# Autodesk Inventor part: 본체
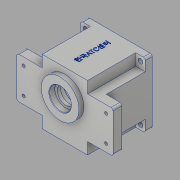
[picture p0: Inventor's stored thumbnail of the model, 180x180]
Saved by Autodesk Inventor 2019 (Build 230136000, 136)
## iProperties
Created: 2020-01
Part Number: 본체
Material: 알루미늄 6061
Document SubType Name: Modeling
Designer: 323-19
Density: 2.7 g/cm^3
Appearance: 알루미늄 - 평지
Mass: 876.381 g
Surface Area: 793.348 cm^2
Volume: 324.585 cm^3
Author: 323-19
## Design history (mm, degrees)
sketch "스케치1"
  geometry: L1 (-47, -47)-(47, -47); L2 (47, -47)-(47, 47); L3 (47, 47)-(-47, 47); L4 (-47, 47)-(-47, -47); L5 (-47, -47)-(47, 47); L6 (47, -47)-(-47, 47); 1 further point
  constraints: 12 end point, 2 midpoint, 2 parallel, 1 horizontal, 1 perpendicular
  dimensions: "d0" = 94 distance of L3.end L2.end; "d1" = 94 distance of L2.end L1.end
extrude "돌출1" new body sketch "스케치1" distance "d2" = 80; taper "d3" = 0 deg
sketch "스케치2"
  geometry: L1 (-70, 30)-(70, 30); L2 (70, 30)-(70, -30); L3 (70, -30)-(-70, -30); L4 (-70, -30)-(-70, 30); L5 (-70, 30)-(70, -30); L6 (70, 30)-(-70, -30); 1 further point
  constraints: 12 end point, 2 midpoint, 2 parallel, 1 horizontal, 1 perpendicular
  dimensions: "d4" = 140 distance of L2.end L3.end; "d5" = 60 distance of L1.end L2.end
extrude "돌출2" join sketch "스케치2" distance "d6" = 13; taper "d7" = 0 deg
sketch "스케치3"
  geometry: C1 r 27.5 at (0, 11); 1 further point
  constraints: 1 centre point, 1 vertical alignment
  dimensions: "d8" = 55 diameter of C1; "d9" = 11 distance of point (0, 0) C1.centre
extrude "돌출3" join sketch "스케치3" distance "d10" = 7; taper "d11" = 0 deg
sketch "스케치4"
  geometry: L1 (70, -30)-(47, -30) reference; L2 (47, -30)-(47, -47) reference; L3 (47, -47)-(-47, -47) reference; L4 (-47, -47)-(-47, -30) reference; L5 (-47, -30)-(-70, -30) reference; L6 (-70, -30)-(-70, 30) reference; L7 (-70, 30)-(-47, 30) reference; L8 (-47, 30)-(-47, 47) reference; L9 (-47, 47)-(47, 47) reference; L10 (47, 47)-(47, 30) reference; L11 (47, 30)-(70, 30) reference; L12 (70, 30)-(70, -30) reference; L13 (47, 30)-(47, 47) reference; L14 (47, 47)-(33, 47); L15 (33, 47)-(33, 30); L16 (33, 30)-(47, 30); L17 (47, 30)-(47, 47); L18 (-47, -47)-(47, -47) reference; L19 (47, -47)-(33, -47); L20 (33, -47)-(33, -30); L21 (33, -30)-(47, -30); L22 (47, -30)-(47, -47); L23 (-47, -47)-(-33, -47); L24 (-33, -47)-(-33, -30); L25 (-33, -30)-(-47, -30); L26 (-47, -30)-(-47, -47); L27 (-47, 47)-(-33, 47); L28 (-33, 47)-(-33, 30); L29 (-33, 30)-(-47, 30); L30 (-47, 30)-(-47, 47); C1 r 27.5 at (0, 11) reference; 1 further point
  constraints: 32 end point, 8 parallel, 4 horizontal, 4 perpendicular
  dimensions: "d12" = 14 distance of L16.end L15.end; "d13" = 17 distance of L15.end L14.end; "d14" = 14 distance of L20.end L21.end; "d15" = 17 distance of L19.end L20.end; "d16" = 14 distance of L25.end L24.end; "d17" = 17 distance of L24.end L23.end; "d18" = 14 distance of L28.end L29.end; "d19" = 17 distance of L27.end L28.end
extrude "돌출4" cut sketch "스케치4" distance "d20" = 70; taper "d21" = 0 deg
sketch "스케치5"
  geometry: C1 r 40 at (0, 0); 1 further point
  constraints: 1 centre point, 1 coincident
  dimensions: "d22" = 80 diameter of C1
extrude "돌출5" cut sketch "스케치5" distance "d23" = 71; taper "d24" = 0 deg
sketch "스케치6"
  geometry: C1 r 43 at (0, 0); 1 further point
  constraints: 1 centre point, 1 coincident
  dimensions: "d25" = 86 diameter of C1
extrude "돌출6" cut sketch "스케치6" distance "d26" = 9; taper "d27" = 0 deg
sketch "스케치7"
  geometry: C1 r 21 at (0, 11); C2 r 15 at (0, -20); 1 further point
  constraints: 2 centre point, 2 vertical alignment
  dimensions: "d28" = 42 diameter of C1; "d29" = 30 diameter of C2; "d30" = 11 distance of point (0, 0) C1.centre; "d31" = 20 distance of point (0, 0) C2.centre
extrude "돌출7" join sketch "스케치7" distance "d32" = 7; taper "d33" = 0 deg
sketch "스케치8"
  geometry: L1 (-47, -30)-(-47, 30) reference; L2 (-47, 30)-(-33, 30) reference; L3 (-33, 30)-(-33, 47) reference; L4 (-33, 47)-(33, 47) reference; L5 (33, 47)-(33, 30) reference; L6 (33, 30)-(47, 30) reference; L7 (47, 30)-(47, -30) reference; L8 (47, -30)-(33, -30) reference; L9 (33, -30)-(33, -47) reference; L10 (33, -47)-(-33, -47) reference; L11 (-33, -47)-(-33, -30) reference; L12 (-33, -30)-(-47, -30) reference; C1 r 40 at (0, 0) reference; C2 r 17.5 at (0, 11); A1 r 21 centre (0, 11) between (8.978, -7.984) and (-8.978, -7.984) reference; A2 r 15 centre (0, -20) between (-8.978, -7.984) and (8.978, -7.984) reference; 1 further point
  constraints: 1 centre point, 1 coincident
  dimensions: "d34" = 35 diameter of C2
extrude "돌출8" cut sketch "스케치8" distance "d35" = 10; taper "d36" = 0 deg
sketch "스케치9"
  geometry: L1 (-47, -30)-(-47, 30) reference; L2 (-47, 30)-(-33, 30) reference; L3 (-33, 30)-(-33, 47) reference; L4 (-33, 47)-(33, 47) reference; L5 (33, 47)-(33, 30) reference; L6 (33, 30)-(47, 30) reference; L7 (47, 30)-(47, -30) reference; L8 (47, -30)-(33, -30) reference; L9 (33, -30)-(33, -47) reference; L10 (33, -47)-(-33, -47) reference; L11 (-33, -47)-(-33, -30) reference; L12 (-33, -30)-(-47, -30) reference; C1 r 17.5 at (0, 11) reference; C2 r 40 at (0, 0) reference; C3 r 11 at (0, -20); A1 r 21 centre (0, 11) between (8.978, -7.984) and (-8.978, -7.984) reference; A2 r 15 centre (0, -20) between (-8.978, -7.984) and (8.978, -7.984) reference; 1 further point
  constraints: 1 centre point, 1 coincident
  dimensions: "d37" = 22 diameter of C3
extrude "돌출9" cut sketch "스케치9" distance "d38" = 7; taper "d39" = 0 deg
sketch "스케치10"
  geometry: L1 (-33, -27)-(-33, -10) reference; L2 (-33, -10)-(-70, -10) reference; L3 (-70, -10)-(-70, 50) reference; L4 (-70, 50)-(-33, 50) reference; L5 (-33, 50)-(-33, 67) reference; L6 (-33, 67)-(33, 67) reference; L7 (33, 67)-(33, 50) reference; L8 (33, 50)-(70, 50) reference; L9 (70, 50)-(70, -10) reference; L10 (70, -10)-(33, -10) reference; L11 (33, -10)-(33, -27) reference; L12 (33, -27)-(-33, -27) reference; C1 r 11 at (0, 0) reference; C2 r 17.5 at (0, 31) reference; C3 r 40 at (0, 20) reference; C4 r 9.5 at (0, 0); A1 r 21 centre (0, 31) between (8.978, 12.016) and (-8.978, 12.016) reference; A2 r 15 centre (0, 0) between (-8.978, 12.016) and (8.978, 12.016) reference; 1 further point
  constraints: 1 centre point, 1 coincident
  dimensions: "d40" = 19 diameter of C4
extrude "돌출10" cut sketch "스케치10" distance "d41" = 3; taper "d42" = 0 deg
sketch "스케치11"
  geometry: C1 r 27.5 at (0, 0) reference; C2 r 16 at (0, 0); 1 further point
  constraints: 1 centre point, 1 coincident
  dimensions: "d43" = 32 diameter of C2
extrude "돌출11" cut sketch "스케치11" distance "d44" = 8.3; taper "d45" = 0 deg
sketch "스케치12"
  geometry: L1 (33, -41)-(33, -58) reference; L2 (33, -58)-(-33, -58) reference; L3 (-33, -58)-(-33, -41) reference; L4 (-33, -41)-(-70, -41) reference; L5 (-70, -41)-(-70, 19) reference; L6 (-70, 19)-(-33, 19) reference; L7 (-33, 19)-(-33, 36) reference; L8 (-33, 36)-(33, 36) reference; L9 (33, 36)-(33, 19) reference; L10 (33, 19)-(70, 19) reference; L11 (70, 19)-(70, -41) reference; L12 (70, -41)-(33, -41) reference; C1 r 16 at (0, 0) reference; C2 r 12.5 at (0, 0); 1 further point
  constraints: 1 centre point, 1 coincident
  dimensions: "d46" = 25 diameter of C2
extrude "돌출12" cut sketch "스케치12" distance "d47" = 4.7; taper "d48" = 0 deg
sketch "스케치13"
  geometry: L1 (47, 47)-(47, -47) reference; L2 (47, -47)-(-47, -47) reference; L3 (-47, -47)-(-47, 47) reference; L4 (-47, 47)-(47, 47) reference; L5 (35.778, 3.994)-(39.8, 3.994); L6 (35.778, -3.994)-(39.8, -3.994); C1 r 43 at (0, 0) reference; C2 r 40 at (0, 0) reference; A1 r 36 centre (0, 0) between (36, 0) and (35.778, 3.994); A2 r 4 centre (36, 0) between (35.778, 3.994) and (35.778, -3.994); A3 r 40 centre (0, 0) between (39.8, 3.994) and (39.8, -3.994) reference; A4 r 40 centre (0, 0) between (39.8, -3.994) and (39.8, 3.994); 1 further point
  constraints: 9 point on circle, 4 end point, 3 centre point, 2 coincident, 1 horizontal, 1 horizontal alignment, 1 parallel
  dimensions: "d49" = 72 diameter of A1; "d50" = 8 diameter of A2
extrude "돌출13" join sketch "스케치13" stored distance "d51" = 4.7; taper "d52" = 0 deg
sketch "스케치14"
  geometry: A1 r 4 centre (-36, 0) between (-35.778, -3.994) and (-35.778, 3.994) reference; A2 r 4 centre (36, 0) between (35.778, 3.994) and (35.778, -3.994) reference; 3 further points
  constraints: 2 coincident
hole "구멍1" sketch "스케치14" at (-36, 0), (36, 0) diameter "d53" = 3.242; stored, may be unused: countersink angle "d57" = 90 deg, drill point angle "d59" = 118 deg; dims "d54" = 7, "d55" = 4, "d56" = 2, "d58" = 9
sketch "스케치16"
  geometry: L1 (47, 47)-(47, -47) reference; L2 (47, -47)-(-47, -47) reference; L3 (-47, -47)-(-47, 47) reference; L4 (-47, 47)-(47, 47) reference; L5 (-40, -40)-(40, -40); L6 (40, -40)-(40, 40); L7 (40, 40)-(-40, 40); L8 (-40, 40)-(-40, -40); L9 (-40, -40)-(40, 40); L10 (40, -40)-(-40, 40); C1 r 43 at (0, 0) reference; 1 further point
  constraints: 12 end point, 2 midpoint, 2 parallel, 1 horizontal, 1 perpendicular
  dimensions: "d60" = 80 distance of L7.end L6.end; "d61" = 80 distance of L6.end L5.end
hole "구멍2" sketch "스케치16" at (40, 40), (-40, 40), (-40, -40), (40, -40) diameter "d62" = 7; stored, may be unused: countersink angle "d66" = 90 deg, drill point angle "d68" = 0 deg; dims "d63" = 7, "d64" = 4, "d65" = 2, "d67" = 10
sketch "스케치17"
  geometry: L1 (35.778, 3.994)-(39.8, 3.994) reference; L2 (-39.8, 3.994)-(-35.778, 3.994) reference; L3 (-35.778, -3.994)-(-39.8, -3.994) reference; L4 (39.8, -3.994)-(35.778, -3.994) reference; L5 (-47, -30)-(-47, 30) reference; L6 (-70, 30)-(-47, 30) reference; L7 (-70, -30)-(-70, 30) reference; L8 (-47, -30)-(-70, -30) reference; L9 (-33, -30)-(-47, -30) reference; L10 (-33, -47)-(-33, -30) reference; L11 (33, -47)-(-33, -47) reference; L12 (33, -30)-(33, -47) reference; L13 (47, -30)-(33, -30) reference; L14 (47, 30)-(47, -30) reference; L15 (47, 30)-(70, 30) reference; L16 (70, 30)-(70, -30) reference; L17 (70, -30)-(47, -30) reference; L18 (-47, 30)-(-33, 30) reference; L19 (-33, 30)-(-33, 47) reference; L20 (-33, 47)-(33, 47) reference; L21 (33, 47)-(33, 30) reference; L22 (33, 30)-(47, 30) reference; L23 (-60, -19)-(60, -19); L24 (60, -19)-(60, 19); L25 (60, 19)-(-60, 19); L26 (-60, 19)-(-60, -19); L27 (-60, -19)-(60, 19); L28 (60, -19)-(-60, 19); C1 r 11 at (0, -20) reference; C2 r 17.5 at (0, 11) reference; A1 r 4 centre (36, 0) between (35.778, 3.994) and (35.778, -3.994) reference; A2 r 40 centre (0, 0) between (39.8, 3.994) and (-39.8, 3.994) reference; A3 r 4 centre (-36, 0) between (-35.778, -3.994) and (-35.778, 3.994) reference; A4 r 40 centre (0, 0) between (-39.8, -3.994) and (39.8, -3.994) reference; A5 r 21 centre (0, 11) between (8.978, -7.984) and (-8.978, -7.984) reference; A6 r 15 centre (0, -20) between (-8.978, -7.984) and (8.978, -7.984) reference; 1 further point
  constraints: 12 end point, 2 midpoint, 2 parallel, 1 horizontal, 1 perpendicular
  dimensions: "d69" = 120 distance of L25.end L24.end; "d70" = 38 distance of L24.end L23.end
hole "구멍3" sketch "스케치17" at (60, 19), (60, -19), (-60, -19), (-60, 19) diameter "d71" = 4.5; stored, may be unused: countersink angle "d75" = 90 deg, drill point angle "d77" = 0 deg; dims "d72" = 7, "d73" = 10, "d74" = 5, "d76" = 13
chamfer "모따기1" distance "d78" = 0.46185; stored, may be unused: second distance "d79" = 2, angle "d80" = 60 deg
chamfer "모따기2" distance "d81" = 1; stored, may be unused: second distance "d82" = 2, angle "d83" = 45 deg
chamfer "모따기3" distance "d84" = 1; stored, may be unused: second distance "d85" = 2, angle "d86" = 45 deg
fillet "모깎기1" dims "d87" = 3
fillet "모깎기2" dims "d88" = 3
fillet "모깎기3" dims "d89" = 3
fillet "모깎기4" dims "d90" = 3
fillet "모깎기5" dims "d91" = 3
node "작업 평면1"
sketch "스케치18"
  geometry: L1 (-11, 80)-(77, 80) reference; 3 further points
  constraints: 1 midpoint, 1 vertical alignment, 1 other
  dimensions: "d93" = 40 distance from line of L1 point (33, 40)
feature "엠보싱1" sketch "스케치18" dims "d0" = 94, "d1" = 94, "d94" = 0.5, "d95" = 0
node "솔리드1"
mirror "미러1"
node "절단 모서리 투영1"
node "절단 모서리 투영2"
node "절단 모서리 투영3"
node "절단 모서리 투영4"
node "절단 모서리 투영5"
node "절단 모서리 투영6"
node "절단 모서리 투영7"
node "절단 모서리 투영10"
node "절단 모서리 투영11"
other parameters: "d92" = 0
